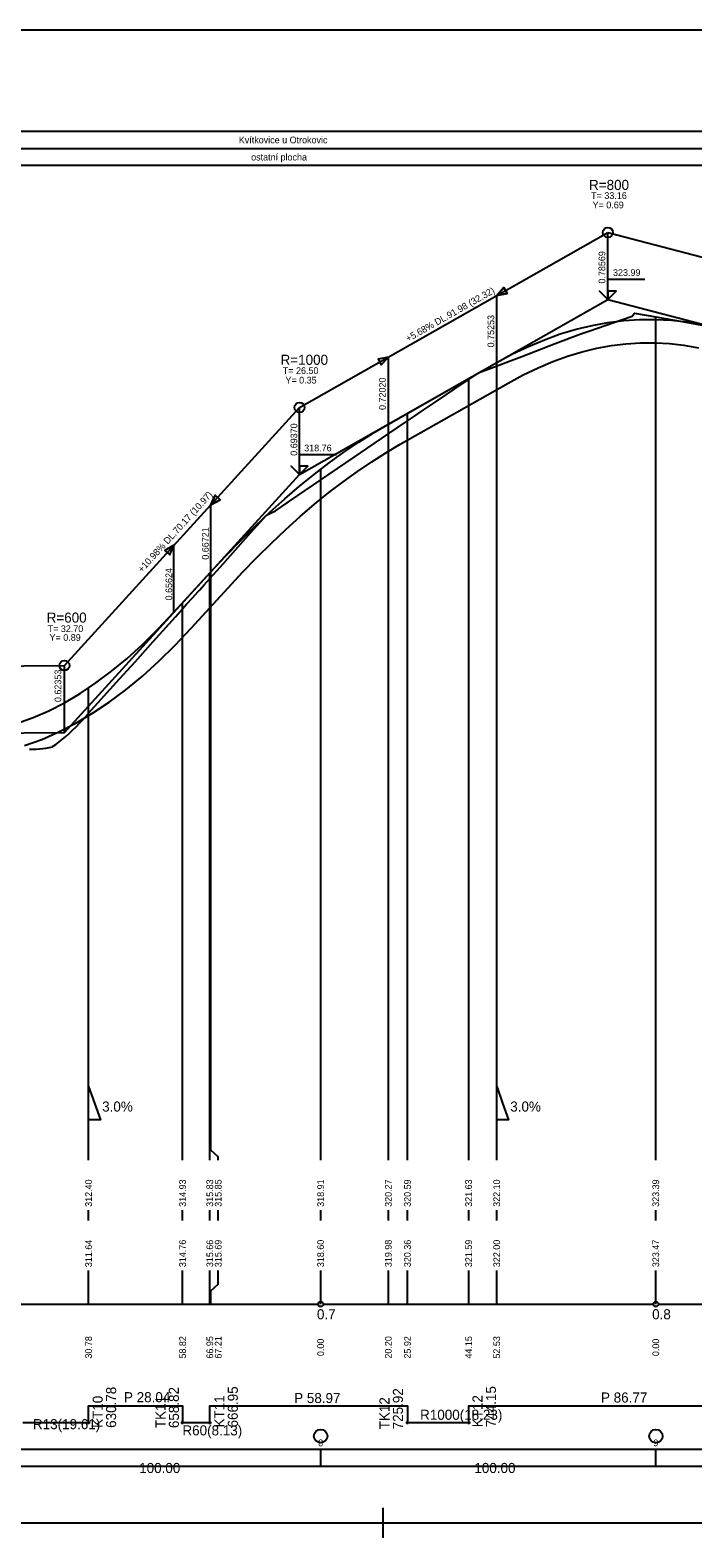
# Model space of a CAD drawing. Extents: x 1290 to 1438, y 129 to 174.
# Drawn here: x 1363.75 to 1383.52, y 128.92 to 173.92 of the extents above; entities that cross this region are included whole.
import ezdxf

# ---------------------------------------------------------------- set-up
doc = ezdxf.new("R2010")
doc.units = 0
for name, color, linetype in [('_drenaz', 7, 'Continuous'), ('KOTA', 7, 'Continuous'), ('NOVY_STAV', 7, 'Continuous'), ('NS_OBLOUK', 7, 'Continuous'), ('REZY_PO', 7, 'Continuous'), ('SESTAVY_REZU_PO', 7, 'Continuous'), ('SKLONOVE_POMERY', 7, 'Continuous'), ('SMEROVE_POMERY', 7, 'Continuous'), ('SMEROVE_POMERY_KOD', 7, 'Continuous'), ('SVK_STAT', 7, 'Continuous'), ('TABULKY', 7, 'Continuous'), ('u_pricne_rezy', 7, 'Continuous'), ('x_formát_rám', 7, 'Continuous')]:
    doc.layers.add(name, color=color, linetype=linetype)

msp = doc.modelspace()

# ---------------------------------------------------------------- linework, layer by layer
at = {"layer": '_drenaz'}
for points in [[(1363.581, 152.566), (1364.094, 152.749), (1364.603, 152.971), (1365.108, 153.231), (1365.61, 153.528), (1366.109, 153.862), (1366.604, 154.232), (1367.096, 154.638), (1367.586, 155.081), (1368.073, 155.558), (1368.554, 156.067), (1369.653, 157.274), (1370.087, 157.741), (1370.518, 158.186), (1370.949, 158.611), (1371.378, 159.017), (1371.807, 159.402), (1372.235, 159.768), (1372.662, 160.115), (1373.089, 160.442), (1373.514, 160.749), (1373.938, 161.036), (1374.361, 161.305), (1374.788, 161.557), (1378.008, 163.386), (1378.461, 163.629), (1378.904, 163.842), (1379.345, 164.027), (1379.784, 164.185), (1380.222, 164.317), (1380.657, 164.423), (1381.092, 164.502), (1381.525, 164.556), (1381.957, 164.584), (1382.39, 164.586), (1382.417, 164.585)], [(1382.417, 164.585), (1382.822, 164.563), (1383.255, 164.514), (1383.689, 164.44)]]:
    msp.add_lwpolyline(points, dxfattribs=at)
at = {"layer": 'KOTA'}
for points in [[(1380.986, 165.882), (1380.736, 166.132), (1380.986, 165.882), (1380.986, 166.482), (1382.086, 166.482)], [(1380.986, 166.132), (1380.986, 165.882), (1381.236, 166.132), (1380.986, 166.132)], [(1380.986, 165.882), (1381.236, 166.132), (1380.986, 166.132)], [(1380.986, 165.882), (1380.986, 165.882)], [(1371.787, 160.658), (1371.537, 160.908), (1371.787, 160.658), (1371.787, 161.258), (1372.887, 161.258)], [(1371.787, 160.908), (1371.787, 160.658), (1372.037, 160.908), (1371.787, 160.908)], [(1371.787, 160.658), (1372.037, 160.908), (1371.787, 160.908)], [(1371.787, 160.658), (1371.787, 160.658)]]:
    msp.add_lwpolyline(points, dxfattribs=at)
at = {"layer": 'NOVY_STAV'}
for points in [[(1371.787, 162.658), (1380.986, 167.882)], [(1380.986, 165.882), (1380.986, 167.882)], [(1380.986, 167.882), (1389.751, 165.594)], [(1352.417, 148.331), (1357.497, 152.896), (1364.77, 152.953), (1371.787, 160.658), (1380.986, 165.882), (1389.751, 163.594), (1398.36, 163.097), (1406.284, 157.825), (1410.009, 157.782)], [(1363.368, 153.233), (1363.836, 153.4), (1364.303, 153.604), (1364.77, 153.844), (1365.237, 154.121), (1365.704, 154.434), (1366.172, 154.783), (1366.639, 155.168), (1367.106, 155.59), (1367.573, 156.049), (1368.04, 156.544), (1369.138, 157.748), (1369.579, 158.223), (1370.021, 158.679), (1370.462, 159.115), (1370.904, 159.532), (1371.346, 159.929), (1371.787, 160.306), (1372.229, 160.665), (1372.671, 161.003), (1373.112, 161.322), (1373.554, 161.622), (1373.995, 161.902), (1374.437, 162.162), (1377.67, 163.998), (1378.143, 164.254), (1378.617, 164.48), (1379.091, 164.679), (1379.564, 164.85), (1380.038, 164.993), (1380.512, 165.108), (1380.985, 165.195), (1381.459, 165.253), (1381.933, 165.284), (1382.407, 165.287), (1382.88, 165.261), (1383.354, 165.208), (1383.828, 165.126)], [(1364.77, 154.953), (1371.787, 162.658)], [(1371.787, 160.658), (1371.787, 162.658)], [(1357.497, 154.896), (1364.77, 154.953)], [(1364.77, 152.953), (1364.77, 154.953)]]:
    msp.add_lwpolyline(points, dxfattribs=at)
for centre in [(1380.986, 167.882), (1371.787, 162.658), (1364.77, 154.953)]:
    msp.add_circle(centre, 0.15, dxfattribs=at)
at = {"layer": 'NS_OBLOUK'}
for points in [[(1377.67, 165.998), (1377.98, 166.06), (1377.881, 166.234), (1377.67, 165.998)], [(1377.67, 163.998), (1377.67, 165.998)], [(1374.226, 163.927), (1374.437, 164.163), (1374.127, 164.101), (1374.226, 163.927)], [(1374.437, 162.163), (1374.437, 164.163)], [(1369.138, 159.748), (1369.414, 159.903), (1369.266, 160.037), (1369.138, 159.748)], [(1369.138, 157.748), (1369.138, 159.748)], [(1367.912, 158.255), (1368.04, 158.544), (1367.764, 158.389), (1367.912, 158.255)], [(1368.04, 156.544), (1368.04, 158.544)]]:
    msp.add_lwpolyline(points, dxfattribs=at)
for points in [[(1377.67, 165.998), (1377.881, 166.234), (1377.98, 166.06)], [(1374.437, 164.163), (1374.127, 164.101), (1374.226, 163.927)], [(1369.138, 159.748), (1369.266, 160.037), (1369.414, 159.903)], [(1368.04, 158.544), (1367.764, 158.389), (1367.912, 158.255)]]:
    msp.add_lwpolyline(points, close=True, dxfattribs=at)
at = {"layer": 'REZY_PO'}
msp.add_lwpolyline([(1363.73, 152.463), (1363.828, 152.459), (1363.926, 152.459), (1364.024, 152.464), (1364.123, 152.474), (1364.221, 152.489), (1364.319, 152.509), (1364.412, 152.532), (1364.417, 152.534), (1364.517, 152.6), (1364.617, 152.673), (1364.717, 152.753), (1364.817, 152.839), (1364.917, 152.93), (1365.017, 153.026), (1365.117, 153.126), (1365.217, 153.23), (1365.317, 153.337), (1365.417, 153.446), (1365.456, 153.489), (1365.494, 153.532), (1365.494, 153.532), (1365.494, 153.532), (1366.417, 154.557), (1366.878, 155.069), (1367.417, 155.667), (1368.084, 156.408), (1368.299, 156.649), (1368.299, 156.649), (1368.299, 156.649), (1368.358, 156.716), (1368.417, 156.782), (1368.591, 156.975), (1368.764, 157.167), (1368.811, 157.218), (1368.938, 157.36), (1369.112, 157.554), (1369.112, 157.554), (1369.112, 157.554), (1369.417, 157.895), (1370.417, 159.013), (1370.802, 159.444), (1370.941, 159.511), (1371.064, 159.574), (1371.417, 159.814), (1371.489, 159.863), (1372.417, 160.494), (1372.417, 160.494), (1373.417, 161.175), (1374.417, 161.856), (1375.009, 162.258), (1375.213, 162.397), (1375.417, 162.536), (1375.917, 162.874), (1376.417, 163.211), (1376.624, 163.35), (1376.832, 163.489), (1377.146, 163.699), (1377.417, 163.802), (1378.417, 164.183), (1379.417, 164.564), (1380.176, 164.853), (1380.417, 164.936), (1381.417, 165.279), (1381.707, 165.378), (1381.778, 165.476), (1382.417, 165.36), (1382.417, 165.36), (1383.417, 165.178), (1384.417, 164.995)], dxfattribs=at)
at = {"layer": 'SESTAVY_REZU_PO'}
for points in [[(1362.492, 135.894), (1372.342, 135.894)], [(1372.492, 135.894), (1382.342, 135.894)], [(1382.492, 135.894), (1392.342, 135.894)]]:
    msp.add_lwpolyline(points, dxfattribs=at)
for centre in [(1372.417, 135.894), (1382.417, 135.894)]:
    msp.add_circle(centre, 0.075, dxfattribs=at)
at = {"layer": 'SKLONOVE_POMERY'}
for points in [[(1365.494, 141.394), (1365.494, 142.394), (1365.494, 142.394), (1365.669, 141.894), (1365.844, 141.394), (1365.494, 141.394)], [(1377.67, 141.394), (1377.67, 142.394), (1377.67, 142.394), (1377.845, 141.894), (1378.02, 141.394), (1377.67, 141.394)]]:
    msp.add_lwpolyline(points, dxfattribs=at)
at = {"layer": 'SMEROVE_POMERY'}
msp.add_lwpolyline([(1363.534, 132.362), (1365.494, 132.362), (1365.494, 132.862), (1368.299, 132.862), (1368.299, 132.362), (1369.112, 132.362), (1369.112, 132.862), (1375.009, 132.862), (1375.009, 132.362), (1376.832, 132.362), (1376.832, 132.862), (1385.509, 132.862)], dxfattribs=at)
at = {"layer": 'SMEROVE_POMERY_KOD'}
for points in [[(1365.444, 132.362), (1365.544, 132.362)], [(1365.494, 132.312), (1365.494, 132.412)], [(1368.249, 132.362), (1368.349, 132.362)], [(1368.299, 132.312), (1368.299, 132.412)], [(1369.062, 132.362), (1369.162, 132.362)], [(1369.112, 132.312), (1369.112, 132.412)], [(1374.959, 132.362), (1375.059, 132.362)], [(1375.009, 132.312), (1375.009, 132.412)], [(1376.782, 132.362), (1376.882, 132.362)], [(1376.832, 132.312), (1376.832, 132.412)]]:
    msp.add_lwpolyline(points, dxfattribs=at)
at = {"layer": 'SVK_STAT'}
for points in [[(1382.417, 140.194), (1382.417, 165.36)], [(1377.67, 140.194), (1377.67, 163.998)], [(1376.832, 140.194), (1376.832, 163.523)], [(1375.009, 140.194), (1375.009, 162.487)], [(1374.437, 140.194), (1374.437, 162.163)], [(1372.417, 140.194), (1372.417, 160.809)], [(1369.112, 140.194), (1369.112, 157.72)], [(1369.362, 140.194), (1369.362, 140.294), (1369.138, 140.494), (1369.138, 157.748)], [(1368.299, 140.194), (1368.299, 156.827)], [(1365.494, 140.194), (1365.494, 154.293)], [(1365.494, 138.394), (1365.494, 138.694)], [(1368.299, 138.394), (1368.299, 138.694)], [(1369.112, 138.394), (1369.112, 138.694)], [(1369.362, 138.394), (1369.362, 138.694)], [(1372.417, 138.394), (1372.417, 138.694)], [(1374.437, 138.394), (1374.437, 138.694)], [(1375.009, 138.394), (1375.009, 138.694)], [(1376.832, 138.394), (1376.832, 138.694)], [(1377.67, 138.394), (1377.67, 138.694)], [(1382.417, 138.394), (1382.417, 138.694)], [(1365.494, 135.894), (1365.494, 136.894)], [(1368.299, 135.894), (1368.299, 136.894)], [(1369.112, 135.894), (1369.112, 136.894)], [(1369.138, 135.894), (1369.138, 136.294), (1369.362, 136.494), (1369.362, 136.894)], [(1372.417, 135.894), (1372.417, 136.894)], [(1374.437, 135.894), (1374.437, 136.894)], [(1375.009, 135.894), (1375.009, 136.894)], [(1376.832, 135.894), (1376.832, 136.894)], [(1377.67, 135.894), (1377.67, 136.894)], [(1382.417, 135.894), (1382.417, 136.894)]]:
    msp.add_lwpolyline(points, dxfattribs=at)
at = {"layer": 'TABULKY'}
for points in [[(1302.417, 169.89), (1410.009, 169.89), (1410.009, 170.89), (1302.417, 170.89), (1302.417, 169.89)], [(1302.417, 170.39), (1410.009, 170.39)]]:
    msp.add_lwpolyline(points, dxfattribs=at)
at = {"layer": 'u_pricne_rezy'}
for points in [[(1302.417, 131.054), (1410.009, 131.054), (1410.009, 131.554), (1302.417, 131.554), (1302.417, 131.054)], [(1372.417, 131.054), (1372.417, 131.554)], [(1382.417, 131.054), (1382.417, 131.554)]]:
    msp.add_lwpolyline(points, dxfattribs=at)
for centre in [(1372.417, 131.954), (1382.417, 131.954)]:
    msp.add_circle(centre, 0.2, dxfattribs=at)
at = {"layer": 'x_formát_rám'}
msp.add_line((1374.283, 128.918), (1374.283, 129.818), dxfattribs=at)
msp.add_lwpolyline([(1290.283, 129.368), (1437.283, 129.368), (1437.283, 173.918), (1290.283, 173.918)], close=True, dxfattribs=at)

# ---------------------------------------------------------------- texts
at = {"layer": 'KOTA'}
for s, p in [('323.99', (1381.138, 166.583)), ('318.76', (1371.925, 161.347))]:
    msp.add_text(s, height=0.2, dxfattribs=at).set_placement(p)
at = {"layer": 'NOVY_STAV'}
for s, rotation, p in [(' 0.78569', 90, (1380.907, 166.281)), ('+5.68% DL.91.98 (32.32)', 29.5953, (1375.025, 164.607)), (' 0.69370', 90, (1371.718, 161.141)), ('+10.98% DL.70.17 (10.97)', 47.6726, (1367.089, 157.717)), (' 0.62353', 90, (1364.677, 153.789))]:
    msp.add_text(s, height=0.2, rotation=rotation, dxfattribs=at).set_placement(p)
at = {"layer": 'NS_OBLOUK'}
for s, height, p in [('R=800', 0.3, (1380.423, 169.149)), ('T= 33.16', 0.2, (1380.486, 168.882)), ('Y= 0.69', 0.2, (1380.529, 168.601)), ('R=1000', 0.3, (1371.22, 163.93)), ('T= 26.50', 0.2, (1371.287, 163.658)), ('Y= 0.35', 0.2, (1371.365, 163.372)), ('R=600', 0.3, (1364.241, 156.235)), ('T= 32.70', 0.2, (1364.27, 155.953)), ('Y= 0.89', 0.2, (1364.328, 155.692))]:
    msp.add_text(s, height=height, dxfattribs=at).set_placement(p)
for s, p in [(' 0.75253', (1377.594, 164.376)), (' 0.72020', (1374.358, 162.508)), (' 0.66721', (1369.077, 158.039)), (' 0.65624', (1367.987, 156.823))]:
    msp.add_text(s, height=0.2, rotation=90, dxfattribs=at).set_placement(p)
at = {"layer": 'SESTAVY_REZU_PO'}
for s, p in [('0.7', (1372.305, 135.442)), ('0.8', (1382.305, 135.442))]:
    msp.add_text(s, height=0.3, dxfattribs=at).set_placement(p)
at = {"layer": 'SKLONOVE_POMERY'}
for p in [(1365.897, 141.642), (1378.072, 141.642)]:
    msp.add_text('3.0%', height=0.3, dxfattribs=at).set_placement(p)
at = {"layer": 'SMEROVE_POMERY'}
for s, p in [('P 28.04', (1366.548, 132.967)), ('P 58.97', (1371.625, 132.942)), ('P 86.77', (1380.779, 132.957)), ('R1000(18.23)', (1375.383, 132.442)), ('R13(19.61)', (1363.833, 132.162)), ('R60(8.13)', (1368.292, 131.976))]:
    msp.add_text(s, height=0.3, dxfattribs=at).set_placement(p)
at = {"layer": 'SMEROVE_POMERY_KOD'}
for s, p in [('630.78', (1366.314, 132.201)), ('658.82', (1368.187, 132.194)), ('666.95', (1369.945, 132.213)), ('725.92', (1374.871, 132.158)), ('744.15', (1377.646, 132.22)), ('KT10', (1365.914, 132.201)), ('TK11', (1367.787, 132.194)), ('KT11', (1369.545, 132.213)), ('TK12', (1374.471, 132.158)), ('KT12', (1377.246, 132.22))]:
    msp.add_text(s, height=0.3, rotation=90, dxfattribs=at).set_placement(p)
at = {"layer": 'SVK_STAT'}
for s, p in [(' 312.40', (1365.591, 138.724)), (' 314.93', (1368.396, 138.724)), (' 315.83', (1369.209, 138.724)), (' 315.85', (1369.459, 138.724)), (' 318.91', (1372.514, 138.724)), (' 320.27', (1374.534, 138.724)), (' 320.59', (1375.106, 138.724)), (' 321.63', (1376.929, 138.724)), (' 322.10', (1377.767, 138.724)), (' 323.39', (1382.514, 138.724)), (' 311.64', (1365.591, 136.924)), (' 314.76', (1368.396, 136.924)), (' 315.66', (1369.209, 136.924)), (' 315.69', (1369.459, 136.924)), (' 318.60', (1372.514, 136.924)), (' 319.98', (1374.534, 136.924)), (' 320.36', (1375.106, 136.924)), (' 321.59', (1376.929, 136.924)), (' 322.00', (1377.767, 136.924)), (' 323.47', (1382.514, 136.924)), (' 30.78', (1365.591, 134.194)), (' 58.82', (1368.396, 134.194)), (' 66.95', (1369.209, 134.194)), (' 67.21', (1369.459, 134.194)), ('  0.00', (1372.514, 134.194)), (' 20.20', (1374.534, 134.194)), (' 25.92', (1375.106, 134.194)), (' 44.15', (1376.929, 134.194)), (' 52.53', (1377.767, 134.194)), ('  0.00', (1382.514, 134.194))]:
    msp.add_text(s, height=0.2, rotation=90, dxfattribs=at).set_placement(p)
at = {"layer": 'TABULKY'}
for s, p in [('Kvítkovice u Otrokovic', (1369.974, 170.542)), ('ostatní plocha', (1370.342, 170.029))]:
    msp.add_text(s, height=0.2, dxfattribs=at).set_placement(p)
at = {"layer": 'u_pricne_rezy'}
for s, height, p in [('8', 0.2, (1372.342, 131.654)), ('9', 0.2, (1382.342, 131.654)), ('100.00', 0.3, (1367.002, 130.854)), ('100.00', 0.3, (1377.002, 130.854))]:
    msp.add_text(s, height=height, dxfattribs=at).set_placement(p)

doc.saveas('drawing.dxf')
